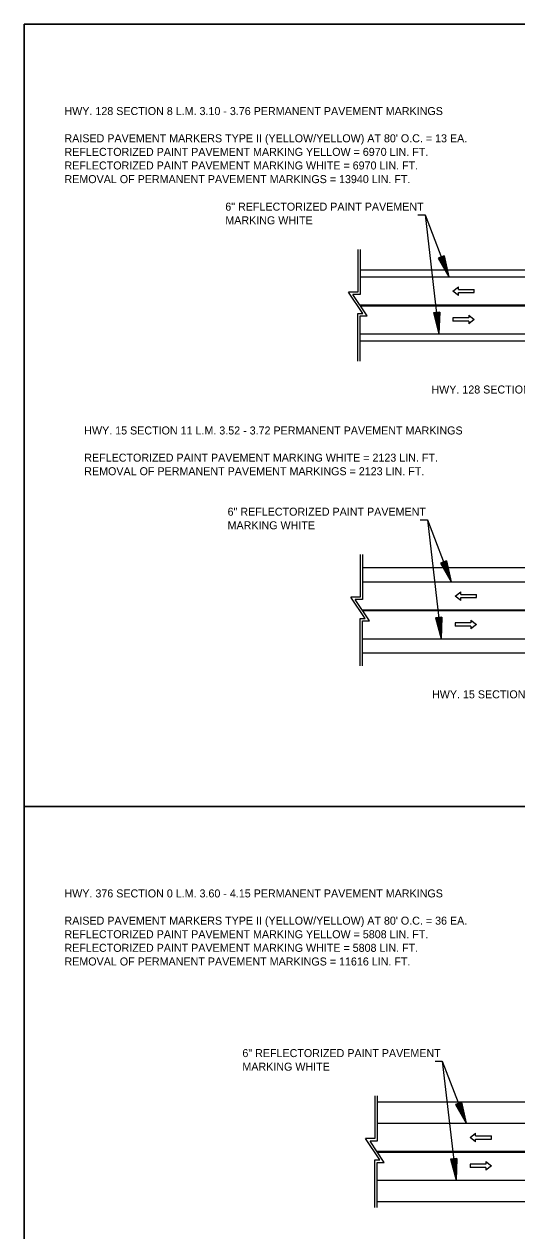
# Model space of a CAD drawing. Extents: x 1372926 to 1373096, y 381240 to 381790.
# Drawn here: x 1372926 to 1372995.2, y 381400.5 to 381570.2 of the extents above; entities that cross this region are included whole.
import ezdxf

# ---------------------------------------------------------------- set-up
doc = ezdxf.new("R2010")
doc.units = 0
for name, color, linetype in [('Default', 7, 'Continuous'), ('DSN_DRFT_Junk-No-Plot', 7, 'Continuous'), ('R_Draft', 7, 'Continuous')]:
    doc.layers.add(name, color=color, linetype=linetype)

msp = doc.modelspace()

# ---------------------------------------------------------------- linework, layer by layer
at = {"layer": 'Default'}
for p, q in [((1372981.31, 381543.36), (1372982.31, 381543.36)), ((1372982.31, 381543.36), (1372985.66, 381534.64)), ((1372982.31, 381543.36), (1372984.26, 381526.64)), ((1372972.85, 381538.48), (1372972.85, 381532.48)), ((1372973.18, 381538.48), (1372973.18, 381532.14)), ((1372985.01, 381537.61), (1372984.17, 381537.28)), ((1372984.17, 381537.28), (1372985.66, 381534.64)), ((1372984.24, 381537.31), (1372985.48, 381535.11)), ((1372984.31, 381537.34), (1372985.3, 381535.59)), ((1372984.38, 381537.37), (1372985.12, 381536.06)), ((1372984.45, 381537.39), (1372984.94, 381536.54)), ((1372984.52, 381537.42), (1372984.76, 381537)), ((1372984.65, 381537.47), (1372984.76, 381537)), ((1372984.72, 381537.5), (1372984.94, 381536.54)), ((1372984.79, 381537.53), (1372985.12, 381536.06)), ((1372984.86, 381537.55), (1372985.3, 381535.59)), ((1372984.94, 381537.58), (1372985.48, 381535.11)), ((1372985.01, 381537.61), (1372985.66, 381534.64)), ((1372986.23, 381532.64), (1372987.01, 381533.24)), ((1372987.01, 381532.87), (1372987.01, 381533.24)), ((1372973.56, 381529.48), (1372971.56, 381532.48)), ((1372972.85, 381532.48), (1372971.56, 381532.48)), ((1372973.18, 381532.14), (1372972.18, 381532.14)), ((1372974.18, 381529.14), (1372972.18, 381532.14)), ((1372987.01, 381532.04), (1372986.23, 381532.64)), ((1372987.01, 381532.87), (1372989.22, 381532.87)), ((1372987.01, 381532.42), (1372989.22, 381532.42)), ((1372987.01, 381532.04), (1372987.01, 381532.42)), ((1372989.22, 381532.42), (1372989.22, 381532.87)), ((1372972.85, 381529.48), (1372973.56, 381529.48)), ((1372972.85, 381522.81), (1372972.85, 381529.48)), ((1372973.18, 381522.81), (1372973.18, 381529.14)), ((1372973.18, 381529.14), (1372974.18, 381529.14)), ((1372984.36, 381529.68), (1372983.47, 381529.57)), ((1372983.47, 381529.57), (1372984.26, 381526.64)), ((1372983.54, 381529.58), (1372984.2, 381527.14)), ((1372983.62, 381529.59), (1372984.14, 381527.65)), ((1372983.69, 381529.6), (1372984.08, 381528.15)), ((1372983.77, 381529.61), (1372984.02, 381528.66)), ((1372983.84, 381529.62), (1372983.97, 381529.15)), ((1372983.98, 381529.63), (1372983.97, 381529.15)), ((1372984.06, 381529.64), (1372984.02, 381528.66)), ((1372984.13, 381529.65), (1372984.08, 381528.15)), ((1372984.21, 381529.66), (1372984.14, 381527.65)), ((1372984.28, 381529.67), (1372984.2, 381527.14)), ((1372984.36, 381529.68), (1372984.26, 381526.64)), ((1372988.44, 381528.87), (1372986.23, 381528.87)), ((1372986.23, 381528.87), (1372986.23, 381528.42)), ((1372988.44, 381528.42), (1372986.23, 381528.42)), ((1372988.44, 381529.24), (1372988.44, 381528.87)), ((1372988.44, 381529.24), (1372989.22, 381528.64)), ((1372989.22, 381528.64), (1372988.44, 381528.04)), ((1372988.44, 381528.42), (1372988.44, 381528.04)), ((1372981.64, 381500.48), (1372982.64, 381500.48)), ((1372982.64, 381500.48), (1372985.98, 381491.76)), ((1372982.64, 381500.48), (1372984.58, 381483.76)), ((1372973.17, 381495.6), (1372973.17, 381489.6)), ((1372973.5, 381495.6), (1372973.5, 381489.26)), ((1372985.33, 381494.73), (1372984.49, 381494.4)), ((1372984.49, 381494.4), (1372985.98, 381491.76)), ((1372984.56, 381494.43), (1372985.8, 381492.23)), ((1372984.63, 381494.46), (1372985.62, 381492.71)), ((1372984.7, 381494.48), (1372985.44, 381493.18)), ((1372984.77, 381494.51), (1372985.26, 381493.65)), ((1372984.84, 381494.54), (1372985.08, 381494.12)), ((1372984.97, 381494.59), (1372985.08, 381494.12)), ((1372985.04, 381494.62), (1372985.26, 381493.65)), ((1372985.12, 381494.64), (1372985.44, 381493.18)), ((1372985.19, 381494.67), (1372985.62, 381492.71)), ((1372985.26, 381494.7), (1372985.8, 381492.23)), ((1372985.33, 381494.73), (1372985.98, 381491.76)), ((1372973.88, 381486.6), (1372971.88, 381489.6)), ((1372973.17, 381489.6), (1372971.88, 381489.6)), ((1372973.5, 381489.26), (1372972.5, 381489.26)), ((1372974.5, 381486.26), (1372972.5, 381489.26)), ((1372986.55, 381489.76), (1372987.33, 381490.36)), ((1372987.33, 381489.16), (1372986.55, 381489.76)), ((1372987.33, 381489.99), (1372987.33, 381490.36)), ((1372987.33, 381489.99), (1372989.54, 381489.99)), ((1372987.33, 381489.54), (1372989.54, 381489.54)), ((1372987.33, 381489.16), (1372987.33, 381489.54)), ((1372989.54, 381489.54), (1372989.54, 381489.99)), ((1372973.17, 381486.6), (1372973.88, 381486.6)), ((1372973.17, 381479.93), (1372973.17, 381486.6)), ((1372973.5, 381479.93), (1372973.5, 381486.26)), ((1372973.5, 381486.26), (1372974.5, 381486.26)), ((1372984.68, 381486.8), (1372983.79, 381486.69)), ((1372983.79, 381486.69), (1372984.58, 381483.76)), ((1372983.86, 381486.7), (1372984.52, 381484.26)), ((1372983.94, 381486.71), (1372984.46, 381484.77)), ((1372984.01, 381486.72), (1372984.41, 381485.27)), ((1372984.09, 381486.73), (1372984.35, 381485.77)), ((1372984.16, 381486.73), (1372984.29, 381486.27)), ((1372984.3, 381486.75), (1372984.29, 381486.27)), ((1372984.38, 381486.76), (1372984.35, 381485.77)), ((1372984.46, 381486.77), (1372984.41, 381485.27)), ((1372984.53, 381486.78), (1372984.46, 381484.77)), ((1372984.61, 381486.79), (1372984.52, 381484.26)), ((1372984.68, 381486.8), (1372984.58, 381483.76)), ((1372988.76, 381485.99), (1372986.55, 381485.99)), ((1372986.55, 381485.99), (1372986.55, 381485.54)), ((1372988.76, 381486.36), (1372988.76, 381485.99)), ((1372988.76, 381486.36), (1372989.54, 381485.76)), ((1372989.54, 381485.76), (1372988.76, 381485.16)), ((1372988.76, 381485.54), (1372986.55, 381485.54)), ((1372988.76, 381485.54), (1372988.76, 381485.16)), ((1372983.71, 381424.36), (1372984.71, 381424.36)), ((1372984.71, 381424.36), (1372988.06, 381415.64)), ((1372984.71, 381424.36), (1372986.66, 381407.64)), ((1372975.25, 381419.48), (1372975.25, 381413.48)), ((1372975.58, 381419.48), (1372975.58, 381413.14)), ((1372987.41, 381418.61), (1372986.57, 381418.28)), ((1372986.57, 381418.28), (1372988.06, 381415.64)), ((1372986.64, 381418.31), (1372987.88, 381416.11)), ((1372986.71, 381418.34), (1372987.7, 381416.59)), ((1372986.78, 381418.37), (1372987.52, 381417.06)), ((1372986.85, 381418.39), (1372987.34, 381417.54)), ((1372986.92, 381418.42), (1372987.16, 381418)), ((1372987.05, 381418.47), (1372987.16, 381418)), ((1372987.12, 381418.5), (1372987.34, 381417.54)), ((1372987.2, 381418.53), (1372987.52, 381417.06)), ((1372987.27, 381418.55), (1372987.7, 381416.59)), ((1372987.34, 381418.58), (1372987.88, 381416.11)), ((1372987.41, 381418.61), (1372988.06, 381415.64)), ((1372975.96, 381410.48), (1372973.96, 381413.48)), ((1372975.25, 381413.48), (1372973.96, 381413.48)), ((1372975.58, 381413.14), (1372974.58, 381413.14)), ((1372976.58, 381410.14), (1372974.58, 381413.14)), ((1372988.63, 381413.64), (1372989.41, 381414.24)), ((1372989.41, 381413.04), (1372988.63, 381413.64)), ((1372989.41, 381413.87), (1372989.41, 381414.24)), ((1372989.41, 381413.87), (1372991.62, 381413.87)), ((1372989.41, 381413.42), (1372991.62, 381413.42)), ((1372989.41, 381413.04), (1372989.41, 381413.42)), ((1372991.62, 381413.42), (1372991.62, 381413.87)), ((1372975.25, 381410.48), (1372975.96, 381410.48)), ((1372975.25, 381403.81), (1372975.25, 381410.48)), ((1372975.58, 381403.81), (1372975.58, 381410.14)), ((1372975.58, 381410.14), (1372976.58, 381410.14)), ((1372986.76, 381410.68), (1372985.87, 381410.57)), ((1372985.87, 381410.57), (1372986.66, 381407.64)), ((1372985.94, 381410.58), (1372986.6, 381408.14)), ((1372986.02, 381410.59), (1372986.54, 381408.65)), ((1372986.09, 381410.6), (1372986.48, 381409.15)), ((1372986.17, 381410.61), (1372986.43, 381409.66)), ((1372986.24, 381410.62), (1372986.37, 381410.15)), ((1372986.38, 381410.63), (1372986.37, 381410.15)), ((1372986.46, 381410.64), (1372986.43, 381409.66)), ((1372986.53, 381410.65), (1372986.48, 381409.15)), ((1372986.61, 381410.66), (1372986.54, 381408.65)), ((1372986.68, 381410.67), (1372986.6, 381408.14)), ((1372986.76, 381410.68), (1372986.66, 381407.64)), ((1372990.84, 381409.87), (1372988.63, 381409.87)), ((1372988.63, 381409.87), (1372988.63, 381409.42)), ((1372990.84, 381409.42), (1372988.63, 381409.42)), ((1372990.84, 381410.24), (1372990.84, 381409.87)), ((1372990.84, 381410.24), (1372991.62, 381409.64)), ((1372991.62, 381409.64), (1372990.84, 381409.04)), ((1372990.84, 381409.42), (1372990.84, 381409.04))]:
    msp.add_line(p, q, dxfattribs=at)
for points in [[(1372925.97, 381570.17), (1372925.97, 381460.17), (1373095.97, 381460.17), (1373095.97, 381570.17)], [(1372925.97, 381460.17), (1372925.97, 381350.17), (1373095.97, 381350.17), (1373095.97, 381460.17)]]:
    msp.add_lwpolyline(points, close=True, dxfattribs=at)
at = {"layer": 'DSN_DRFT_Junk-No-Plot'}
for points in [[(1372925.97, 381570.17), (1373095.97, 381570.17), (1373095.97, 381460.17), (1372925.97, 381460.17)], [(1372925.97, 381570.17), (1372925.97, 381460.17), (1373095.97, 381460.17), (1373095.97, 381570.17)], [(1372925.97, 381460.17), (1373095.97, 381460.17), (1373095.97, 381350.17), (1372925.97, 381350.17)], [(1372925.97, 381460.17), (1372925.97, 381350.17), (1373095.97, 381350.17), (1373095.97, 381460.17)]]:
    msp.add_lwpolyline(points, close=True, dxfattribs=at)
at = {"layer": 'R_Draft'}
for p, q in [((1372973.18, 381535.64), (1373049.57, 381535.64)), ((1372973.18, 381534.64), (1373049.57, 381534.64)), ((1372973.15, 381530.69), (1373049.54, 381530.69)), ((1372973.21, 381530.59), (1373049.61, 381530.59)), ((1372973.18, 381526.64), (1373049.57, 381526.64)), ((1372973.18, 381525.64), (1373049.57, 381525.64)), ((1372973.5, 381493.76), (1373049.89, 381493.76)), ((1372973.5, 381491.76), (1373049.89, 381491.76)), ((1372973.47, 381487.81), (1373049.86, 381487.81)), ((1372973.54, 381487.71), (1373049.93, 381487.71)), ((1372973.5, 381483.76), (1373049.89, 381483.76)), ((1372973.5, 381481.76), (1373049.89, 381481.76)), ((1372975.58, 381418.64), (1373051.97, 381418.64)), ((1372975.58, 381415.64), (1373051.97, 381415.64)), ((1372975.55, 381411.69), (1373051.94, 381411.69)), ((1372975.62, 381411.59), (1373052.01, 381411.59)), ((1372975.58, 381407.64), (1373051.97, 381407.64)), ((1372975.58, 381404.64), (1373051.97, 381404.64))]:
    msp.add_line(p, q, dxfattribs=at)

# ---------------------------------------------------------------- texts
at = {"layer": 'Default'}
for s, p in [('HWY. 128 SECTION 8 L.M. 3.10 - 3.76 PERMANENT PAVEMENT MARKINGS', (1372931.64, 381557.39)), ("RAISED PAVEMENT MARKERS TYPE II (YELLOW/YELLOW) AT 80' O.C. = 13 EA.", (1372931.64, 381553.56)), ('REFLECTORIZED PAINT PAVEMENT MARKING YELLOW = 6970 LIN. FT.', (1372931.64, 381551.65)), ('REFLECTORIZED PAINT PAVEMENT MARKING WHITE = 6970 LIN. FT.', (1372931.64, 381549.74)), ('REMOVAL OF PERMANENT PAVEMENT MARKINGS = 13940 LIN. FT.', (1372931.64, 381547.82)), ('6" REFLECTORIZED PAINT PAVEMENT ', (1372954.24, 381543.95)), ('MARKING WHITE ', (1372954.24, 381542.03)), ('HWY. 15 SECTION 11 L.M. 3.52 - 3.72 PERMANENT PAVEMENT MARKINGS', (1372934.42, 381512.48)), ('REFLECTORIZED PAINT PAVEMENT MARKING WHITE = 2123 LIN. FT.', (1372934.42, 381508.66)), ('REMOVAL OF PERMANENT PAVEMENT MARKINGS = 2123 LIN. FT.', (1372934.42, 381506.75)), ('6" REFLECTORIZED PAINT PAVEMENT ', (1372954.56, 381501.06)), ('MARKING WHITE ', (1372954.56, 381499.15)), ('HWY. 376 SECTION 0 L.M. 3.60 - 4.15 PERMANENT PAVEMENT MARKINGS', (1372931.64, 381447.39)), ("RAISED PAVEMENT MARKERS TYPE II (YELLOW/YELLOW) AT 80' O.C. = 36 EA.", (1372931.64, 381443.56)), ('REFLECTORIZED PAINT PAVEMENT MARKING YELLOW = 5808 LIN. FT.', (1372931.64, 381441.65)), ('REFLECTORIZED PAINT PAVEMENT MARKING WHITE = 5808 LIN. FT.', (1372931.64, 381439.74)), ('REMOVAL OF PERMANENT PAVEMENT MARKINGS = 11616 LIN. FT.', (1372931.64, 381437.82)), ('6" REFLECTORIZED PAINT PAVEMENT ', (1372956.64, 381424.94)), ('MARKING WHITE ', (1372956.64, 381423.03))]:
    msp.add_text(s, height=1.125, dxfattribs=at).set_placement(p)
at = {"layer": 'R_Draft'}
for s, p in [('HWY. 128 SECTION 8 L.M. 3.10 - 3.76 PERMANENT PAVEMENT MARKINGS', (1372983.2, 381518.24)), ('HWY. 15 SECTION 11 L.M. 3.52 - 3.72 PERMANENT PAVEMENT MARKINGS', (1372983.29, 381475.38))]:
    msp.add_text(s, height=1.125, dxfattribs=at).set_placement(p)

doc.saveas('drawing.dxf')
